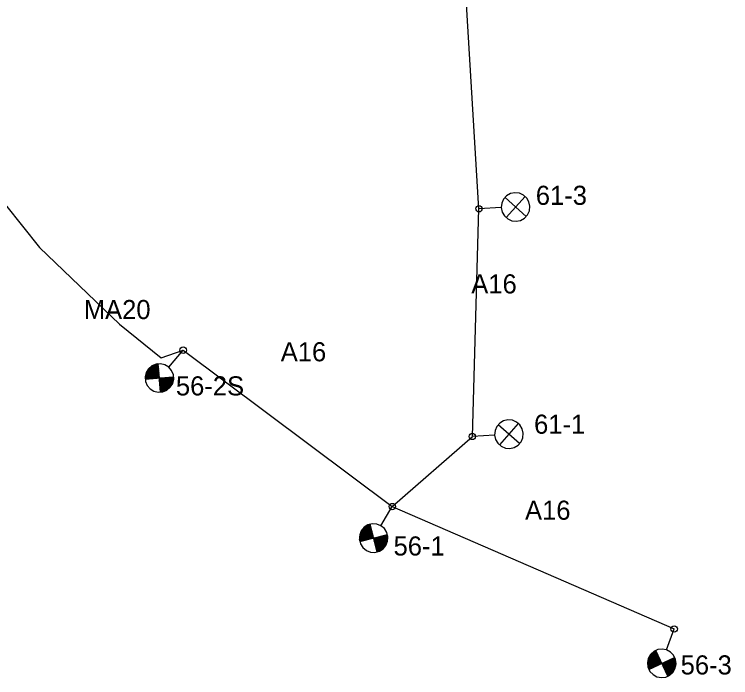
# Model space of a CAD drawing. Extents: x 25497851 to 25498523, y 6686544 to 6687372.
# Drawn here: x 25498410.2 to 25498522.7, y 6687152.3 to 6687256.4 of the extents above; entities that cross this region are included whole.
import ezdxf

# ---------------------------------------------------------------- set-up
doc = ezdxf.new("R2010")
doc.units = 0
for name, color, linetype in [('EL_CABLE_ILMA', 7, 'Continuous'), ('EL_CABLE_MAA', 7, 'Continuous'), ('KEYGWT_ANNOTATION', 7, 'Continuous'), ('Taso 1', 7, 'Continuous'), ('Taso 50', 7, 'Continuous')]:
    doc.layers.add(name, color=color, linetype=linetype)

msp = doc.modelspace()

# ---------------------------------------------------------------- linework, layer by layer
at = {"layer": 'EL_CABLE_ILMA'}
for points in [[(25498469.54, 6687179.13), (25498482.11, 6687190.14), (25498483.15, 6687225.9), (25498480.55, 6687268.5), (25498477.8, 6687311.51), (25498474.29, 6687356.63)], [(25498436.71, 6687203.69), (25498469.54, 6687179.13)], [(25498469.54, 6687179.13), (25498513.79, 6687159.91)]]:
    msp.add_lwpolyline(points, dxfattribs=at)
at = {"layer": 'EL_CABLE_MAA'}
msp.add_lwpolyline([(25498392.6, 6687233.36), (25498390.46, 6687235.76), (25498396.87, 6687241.57), (25498408.81, 6687226.51), (25498414.15, 6687219.81), (25498426.73, 6687207.77), (25498433.27, 6687202.5), (25498436.71, 6687203.69)], dxfattribs=at)
at = {"layer": 'Taso 1'}
for p, q in [((25498490.54, 6687224.68), (25498487.25, 6687227.67)), ((25498490.39, 6687227.82), (25498487.4, 6687224.53)), ((25498486.65, 6687226.07), (25498483.15, 6687225.9)), ((25498434.44, 6687201.03), (25498436.71, 6687203.69)), ((25498433.15, 6687197.1), (25498432.8, 6687201.53)), ((25498430.76, 6687199.14), (25498435.19, 6687199.49)), ((25498489.51, 6687189.03), (25498486.18, 6687191.97)), ((25498489.32, 6687192.17), (25498486.38, 6687188.84)), ((25498485.6, 6687190.36), (25498482.11, 6687190.14)), ((25498467.76, 6687176.12), (25498469.54, 6687179.13)), ((25498467.16, 6687172.03), (25498466.06, 6687176.34)), ((25498464.46, 6687173.63), (25498468.76, 6687174.74)), ((25498512.61, 6687156.62), (25498513.79, 6687159.91)), ((25498512.79, 6687152.49), (25498510.9, 6687156.51)), ((25498509.84, 6687153.56), (25498513.86, 6687155.45))]:
    msp.add_line(p, q, dxfattribs=at)
for points in [[(25498491.14, 6687226.28), (25498491, 6687226.97), (25498490.65, 6687227.58), (25498490.13, 6687228.05), (25498489.49, 6687228.34), (25498488.79, 6687228.42), (25498488.1, 6687228.28), (25498487.49, 6687227.93), (25498487.02, 6687227.41), (25498486.73, 6687226.77), (25498486.65, 6687226.07), (25498486.79, 6687225.38), (25498487.14, 6687224.77), (25498487.66, 6687224.29), (25498488.3, 6687224), (25498489, 6687223.93), (25498489.69, 6687224.07), (25498490.3, 6687224.42), (25498490.78, 6687224.94), (25498491.07, 6687225.58)], [(25498431.52, 6687197.61), (25498432.12, 6687197.24), (25498432.8, 6687197.08), (25498433.5, 6687197.13), (25498434.15, 6687197.4), (25498434.69, 6687197.86), (25498435.06, 6687198.46), (25498435.22, 6687199.14), (25498435.17, 6687199.84), (25498434.9, 6687200.49), (25498434.44, 6687201.03), (25498433.84, 6687201.4), (25498433.15, 6687201.56), (25498432.45, 6687201.51), (25498431.8, 6687201.24), (25498431.27, 6687200.78), (25498430.9, 6687200.18), (25498430.74, 6687199.5), (25498430.79, 6687198.79), (25498431.06, 6687198.14)], [(25498490.09, 6687190.64), (25498489.94, 6687191.33), (25498489.58, 6687191.94), (25498489.05, 6687192.4), (25498488.41, 6687192.68), (25498487.7, 6687192.75), (25498487.02, 6687192.6), (25498486.41, 6687192.24), (25498485.95, 6687191.71), (25498485.67, 6687191.06), (25498485.6, 6687190.36), (25498485.75, 6687189.68), (25498486.11, 6687189.07), (25498486.64, 6687188.6), (25498487.29, 6687188.32), (25498487.99, 6687188.26), (25498488.67, 6687188.41), (25498489.28, 6687188.77), (25498489.75, 6687189.3), (25498490.02, 6687189.94)], [(25498465.47, 6687172.25), (25498466.12, 6687171.99), (25498466.82, 6687171.94), (25498467.51, 6687172.12), (25498468.1, 6687172.5), (25498468.55, 6687173.04), (25498468.81, 6687173.69), (25498468.85, 6687174.4), (25498468.68, 6687175.08), (25498468.3, 6687175.67), (25498467.76, 6687176.12), (25498467.1, 6687176.38), (25498466.4, 6687176.42), (25498465.72, 6687176.25), (25498465.12, 6687175.87), (25498464.67, 6687175.33), (25498464.42, 6687174.68), (25498464.37, 6687173.97), (25498464.55, 6687173.29), (25498464.92, 6687172.7)], [(25498511.08, 6687152.39), (25498511.78, 6687152.26), (25498512.47, 6687152.34), (25498513.11, 6687152.64), (25498513.62, 6687153.13), (25498513.96, 6687153.74), (25498514.09, 6687154.43), (25498514.01, 6687155.13), (25498513.71, 6687155.77), (25498513.22, 6687156.28), (25498512.61, 6687156.62), (25498511.92, 6687156.75), (25498511.22, 6687156.66), (25498510.58, 6687156.37), (25498510.07, 6687155.88), (25498509.73, 6687155.27), (25498509.6, 6687154.58), (25498509.69, 6687153.88), (25498509.99, 6687153.24), (25498510.47, 6687152.73)]]:
    msp.add_lwpolyline(points, close=True, dxfattribs=at)
for centre in [(25498483.15, 6687225.9), (25498436.71, 6687203.69), (25498482.11, 6687190.14), (25498469.54, 6687179.13), (25498513.79, 6687159.91)]:
    msp.add_circle(centre, 0.5, dxfattribs=at)
at = {"layer": 'Taso 50'}
for p, q in [((25498432.91, 6687199.31), (25498431.23, 6687200.74)), ((25498432.84, 6687199.31), (25498431.24, 6687200.67)), ((25498432.98, 6687199.32), (25498431.27, 6687200.78)), ((25498432.97, 6687199.39), (25498431.3, 6687200.82)), ((25498432.97, 6687199.46), (25498431.37, 6687200.82)), ((25498432.96, 6687199.53), (25498431.4, 6687200.86)), ((25498432.96, 6687199.6), (25498431.43, 6687200.9)), ((25498432.95, 6687199.67), (25498431.47, 6687200.94)), ((25498432.94, 6687199.74), (25498431.5, 6687200.98)), ((25498432.94, 6687199.81), (25498431.54, 6687201.01)), ((25498432.93, 6687199.88), (25498431.6, 6687201.02)), ((25498432.93, 6687199.95), (25498431.64, 6687201.06)), ((25498432.92, 6687200.02), (25498431.67, 6687201.09)), ((25498432.92, 6687200.09), (25498431.7, 6687201.13)), ((25498432.91, 6687200.16), (25498431.73, 6687201.17)), ((25498432.91, 6687200.23), (25498431.77, 6687201.21)), ((25498432.9, 6687200.31), (25498431.8, 6687201.24)), ((25498432.89, 6687200.38), (25498431.87, 6687201.25)), ((25498432.89, 6687200.45), (25498431.94, 6687201.26)), ((25498432.88, 6687200.52), (25498431.97, 6687201.3)), ((25498432.88, 6687200.59), (25498432.04, 6687201.3)), ((25498432.87, 6687200.66), (25498432.07, 6687201.34)), ((25498432.87, 6687200.73), (25498432.12, 6687201.36)), ((25498432.86, 6687200.8), (25498432.18, 6687201.38)), ((25498432.86, 6687200.87), (25498432.25, 6687201.39)), ((25498432.85, 6687200.94), (25498432.28, 6687201.43)), ((25498432.84, 6687201.01), (25498432.35, 6687201.43)), ((25498432.84, 6687201.08), (25498432.38, 6687201.47)), ((25498432.83, 6687201.15), (25498432.45, 6687201.48)), ((25498432.83, 6687201.22), (25498432.49, 6687201.51)), ((25498432.82, 6687201.29), (25498432.56, 6687201.52)), ((25498432.82, 6687201.36), (25498432.63, 6687201.52)), ((25498432.81, 6687201.43), (25498432.7, 6687201.53)), ((25498431.22, 6687199.18), (25498430.76, 6687199.57)), ((25498431.36, 6687199.19), (25498430.79, 6687199.68)), ((25498431.29, 6687199.19), (25498430.79, 6687199.61)), ((25498431.5, 6687199.2), (25498430.81, 6687199.79)), ((25498431.43, 6687199.2), (25498430.82, 6687199.72)), ((25498431.64, 6687199.21), (25498430.84, 6687199.89)), ((25498431.57, 6687199.21), (25498430.85, 6687199.82)), ((25498431.78, 6687199.22), (25498430.87, 6687200)), ((25498431.71, 6687199.22), (25498430.87, 6687199.93)), ((25498431.92, 6687199.23), (25498430.89, 6687200.11)), ((25498431.99, 6687199.24), (25498430.9, 6687200.18)), ((25498431.85, 6687199.23), (25498430.9, 6687200.04)), ((25498432.06, 6687199.25), (25498430.92, 6687200.22)), ((25498432.13, 6687199.25), (25498430.95, 6687200.26)), ((25498432.2, 6687199.26), (25498430.99, 6687200.3)), ((25498432.27, 6687199.26), (25498431.02, 6687200.33)), ((25498432.34, 6687199.27), (25498431.05, 6687200.37)), ((25498432.48, 6687199.28), (25498431.08, 6687200.48)), ((25498432.41, 6687199.27), (25498431.08, 6687200.41)), ((25498432.55, 6687199.28), (25498431.11, 6687200.52)), ((25498432.63, 6687199.29), (25498431.14, 6687200.56)), ((25498432.7, 6687199.3), (25498431.18, 6687200.59)), ((25498432.77, 6687199.3), (25498431.21, 6687200.63)), ((25498431.15, 6687199.17), (25498430.73, 6687199.53)), ((25498430.93, 6687199.16), (25498430.74, 6687199.32)), ((25498430.86, 6687199.15), (25498430.75, 6687199.25)), ((25498431.07, 6687199.17), (25498430.77, 6687199.43)), ((25498431, 6687199.16), (25498430.78, 6687199.36)), ((25498432.84, 6687198.85), (25498432.84, 6687198.85)), ((25498434.69, 6687197.86), (25498432.98, 6687199.32)), ((25498434.66, 6687197.82), (25498432.98, 6687199.25)), ((25498434.59, 6687197.81), (25498432.99, 6687199.18)), ((25498434.55, 6687197.78), (25498432.99, 6687199.11)), ((25498434.52, 6687197.74), (25498433, 6687199.04)), ((25498433.01, 6687198.9), (25498434.46, 6687197.66)), ((25498434.42, 6687197.63), (25498433.02, 6687198.83)), ((25498433.02, 6687198.75), (25498434.35, 6687197.62)), ((25498434.32, 6687197.58), (25498433.03, 6687198.68)), ((25498434.29, 6687197.54), (25498433.03, 6687198.61)), ((25498434.49, 6687197.7), (25498433.04, 6687198.93)), ((25498434.26, 6687197.5), (25498433.04, 6687198.54)), ((25498434.22, 6687197.47), (25498433.04, 6687198.47)), ((25498434.72, 6687197.89), (25498433.05, 6687199.32)), ((25498433.12, 6687199.33), (25498434.72, 6687197.97)), ((25498433.19, 6687199.33), (25498434.75, 6687198)), ((25498433.26, 6687199.34), (25498434.78, 6687198.04)), ((25498433.33, 6687199.35), (25498434.81, 6687198.08)), ((25498433.4, 6687199.35), (25498434.85, 6687198.12)), ((25498433.47, 6687199.36), (25498434.87, 6687198.16)), ((25498433.54, 6687199.36), (25498434.87, 6687198.23)), ((25498433.61, 6687199.37), (25498434.91, 6687198.26)), ((25498433.68, 6687199.37), (25498434.94, 6687198.3)), ((25498433.75, 6687199.38), (25498434.97, 6687198.34)), ((25498433.82, 6687199.38), (25498434.96, 6687198.41)), ((25498433.89, 6687199.39), (25498435, 6687198.45)), ((25498433.96, 6687199.4), (25498435.03, 6687198.49)), ((25498434.04, 6687199.4), (25498435.06, 6687198.52)), ((25498434.11, 6687199.41), (25498435.06, 6687198.6)), ((25498434.18, 6687199.41), (25498435.09, 6687198.63)), ((25498434.25, 6687199.42), (25498435.08, 6687198.7)), ((25498434.32, 6687199.42), (25498435.12, 6687198.74)), ((25498434.39, 6687199.43), (25498435.11, 6687198.81)), ((25498434.46, 6687199.43), (25498435.14, 6687198.85)), ((25498434.53, 6687199.44), (25498435.14, 6687198.92)), ((25498434.6, 6687199.45), (25498435.17, 6687198.96)), ((25498434.67, 6687199.45), (25498435.16, 6687199.03)), ((25498434.74, 6687199.46), (25498435.2, 6687199.07)), ((25498434.81, 6687199.46), (25498435.19, 6687199.14)), ((25498434.88, 6687199.47), (25498435.19, 6687199.21)), ((25498434.95, 6687199.47), (25498435.22, 6687199.25)), ((25498435.02, 6687199.48), (25498435.21, 6687199.32)), ((25498435.09, 6687199.48), (25498435.21, 6687199.39)), ((25498433.05, 6687198.4), (25498434.19, 6687197.43)), ((25498433.06, 6687198.33), (25498434.12, 6687197.42)), ((25498433.06, 6687198.26), (25498434.09, 6687197.38)), ((25498433.07, 6687198.19), (25498434.02, 6687197.38)), ((25498433.07, 6687198.12), (25498433.98, 6687197.34)), ((25498433.08, 6687198.05), (25498433.91, 6687197.33)), ((25498433.08, 6687197.98), (25498433.88, 6687197.3)), ((25498433.09, 6687197.91), (25498433.81, 6687197.29)), ((25498433.09, 6687197.84), (25498433.78, 6687197.25)), ((25498433.1, 6687197.77), (25498433.71, 6687197.25)), ((25498433.11, 6687197.7), (25498433.68, 6687197.21)), ((25498433.11, 6687197.63), (25498433.61, 6687197.2)), ((25498433.12, 6687197.56), (25498433.57, 6687197.17)), ((25498433.12, 6687197.49), (25498433.5, 6687197.16)), ((25498433.13, 6687197.41), (25498433.43, 6687197.16)), ((25498433.13, 6687197.34), (25498433.4, 6687197.12)), ((25498433.14, 6687197.27), (25498433.33, 6687197.11)), ((25498433.14, 6687197.2), (25498433.22, 6687197.14)), ((25498466.31, 6687175.35), (25498465.28, 6687175.96)), ((25498466.29, 6687175.42), (25498465.35, 6687175.98)), ((25498466.28, 6687175.48), (25498465.37, 6687176.02)), ((25498466.26, 6687175.55), (25498465.42, 6687176.05)), ((25498466.24, 6687175.62), (25498465.47, 6687176.08)), ((25498466.22, 6687175.69), (25498465.54, 6687176.1)), ((25498466.21, 6687175.76), (25498465.56, 6687176.14)), ((25498466.19, 6687175.83), (25498465.63, 6687176.16)), ((25498466.17, 6687175.9), (25498465.66, 6687176.2)), ((25498466.15, 6687175.96), (25498465.72, 6687176.22)), ((25498466.14, 6687176.03), (25498465.75, 6687176.26)), ((25498466.12, 6687176.1), (25498465.82, 6687176.28)), ((25498466.1, 6687176.17), (25498465.89, 6687176.3)), ((25498466.08, 6687176.24), (25498465.95, 6687176.31)), ((25498465.86, 6687173.99), (25498464.48, 6687174.8)), ((25498465.93, 6687174.01), (25498464.51, 6687174.85)), ((25498465.99, 6687174.03), (25498464.53, 6687174.89)), ((25498466.13, 6687174.06), (25498464.55, 6687175)), ((25498466.2, 6687174.08), (25498464.56, 6687175.05)), ((25498466.06, 6687174.04), (25498464.56, 6687174.93)), ((25498466.27, 6687174.1), (25498464.59, 6687175.09)), ((25498466.34, 6687174.11), (25498464.62, 6687175.13)), ((25498466.41, 6687174.13), (25498464.64, 6687175.17)), ((25498466.54, 6687174.17), (25498464.65, 6687175.29)), ((25498466.61, 6687174.18), (25498464.67, 6687175.33)), ((25498466.47, 6687174.15), (25498464.67, 6687175.22)), ((25498466.59, 6687174.25), (25498464.7, 6687175.37)), ((25498466.58, 6687174.32), (25498464.77, 6687175.39)), ((25498466.56, 6687174.39), (25498464.79, 6687175.43)), ((25498466.54, 6687174.46), (25498464.82, 6687175.48)), ((25498466.52, 6687174.53), (25498464.84, 6687175.52)), ((25498466.51, 6687174.59), (25498464.87, 6687175.56)), ((25498466.49, 6687174.66), (25498464.9, 6687175.6)), ((25498466.47, 6687174.73), (25498464.96, 6687175.62)), ((25498466.45, 6687174.8), (25498464.99, 6687175.67)), ((25498466.44, 6687174.87), (25498465.02, 6687175.71)), ((25498466.42, 6687174.94), (25498465.04, 6687175.75)), ((25498466.4, 6687175.01), (25498465.07, 6687175.79)), ((25498466.38, 6687175.07), (25498465.09, 6687175.84)), ((25498466.36, 6687175.14), (25498465.12, 6687175.87)), ((25498466.35, 6687175.21), (25498465.19, 6687175.9)), ((25498466.33, 6687175.28), (25498465.25, 6687175.92)), ((25498464.83, 6687173.73), (25498464.36, 6687174.01)), ((25498464.9, 6687173.74), (25498464.38, 6687174.05)), ((25498465.04, 6687173.78), (25498464.39, 6687174.16)), ((25498465.17, 6687173.81), (25498464.4, 6687174.27)), ((25498465.45, 6687173.88), (25498464.41, 6687174.5)), ((25498465.31, 6687173.85), (25498464.41, 6687174.38)), ((25498464.97, 6687173.76), (25498464.41, 6687174.09)), ((25498464.62, 6687173.67), (25498464.41, 6687173.8)), ((25498465.65, 6687173.94), (25498464.42, 6687174.68)), ((25498465.58, 6687173.92), (25498464.42, 6687174.61)), ((25498465.24, 6687173.83), (25498464.42, 6687174.32)), ((25498465.1, 6687173.8), (25498464.42, 6687174.2)), ((25498464.76, 6687173.71), (25498464.42, 6687173.91)), ((25498465.72, 6687173.95), (25498464.43, 6687174.72)), ((25498465.38, 6687173.87), (25498464.43, 6687174.43)), ((25498464.56, 6687173.66), (25498464.43, 6687173.73)), ((25498465.52, 6687173.9), (25498464.44, 6687174.54)), ((25498464.69, 6687173.69), (25498464.44, 6687173.84)), ((25498465.79, 6687173.97), (25498464.46, 6687174.76)), ((25498466.55, 6687173.69), (25498466.55, 6687173.69)), ((25498468.55, 6687173.04), (25498466.61, 6687174.18)), ((25498468.52, 6687173), (25498466.63, 6687174.11)), ((25498468.45, 6687172.98), (25498466.65, 6687174.05)), ((25498468.43, 6687172.93), (25498466.66, 6687173.98)), ((25498468.57, 6687173.08), (25498466.68, 6687174.2)), ((25498468.4, 6687172.89), (25498466.68, 6687173.91)), ((25498466.72, 6687173.77), (25498468.35, 6687172.81)), ((25498468.38, 6687172.85), (25498466.74, 6687173.82)), ((25498468.32, 6687172.77), (25498466.74, 6687173.71)), ((25498466.75, 6687174.22), (25498468.56, 6687173.15)), ((25498466.82, 6687174.24), (25498468.58, 6687173.19)), ((25498466.89, 6687174.25), (25498468.61, 6687173.24)), ((25498466.95, 6687174.27), (25498468.63, 6687173.28)), ((25498467.02, 6687174.29), (25498468.66, 6687173.32)), ((25498467.09, 6687174.31), (25498468.68, 6687173.37)), ((25498467.16, 6687174.32), (25498468.67, 6687173.43)), ((25498467.23, 6687174.34), (25498468.69, 6687173.48)), ((25498467.3, 6687174.36), (25498468.72, 6687173.52)), ((25498467.36, 6687174.38), (25498468.74, 6687173.56)), ((25498467.43, 6687174.39), (25498468.72, 6687173.63)), ((25498467.5, 6687174.41), (25498468.75, 6687173.67)), ((25498467.57, 6687174.43), (25498468.77, 6687173.72)), ((25498467.64, 6687174.45), (25498468.8, 6687173.76)), ((25498467.71, 6687174.46), (25498468.78, 6687173.83)), ((25498467.78, 6687174.48), (25498468.81, 6687173.87)), ((25498467.84, 6687174.5), (25498468.79, 6687173.94)), ((25498467.91, 6687174.52), (25498468.82, 6687173.98)), ((25498467.98, 6687174.54), (25498468.8, 6687174.05)), ((25498468.05, 6687174.55), (25498468.82, 6687174.09)), ((25498468.12, 6687174.57), (25498468.81, 6687174.16)), ((25498468.19, 6687174.59), (25498468.83, 6687174.21)), ((25498468.25, 6687174.61), (25498468.81, 6687174.27)), ((25498468.32, 6687174.62), (25498468.84, 6687174.32)), ((25498468.39, 6687174.64), (25498468.82, 6687174.39)), ((25498468.46, 6687174.66), (25498468.8, 6687174.45)), ((25498468.53, 6687174.68), (25498468.83, 6687174.5)), ((25498468.6, 6687174.69), (25498468.81, 6687174.57)), ((25498468.67, 6687174.71), (25498468.79, 6687174.63)), ((25498466.75, 6687173.64), (25498468.26, 6687172.74)), ((25498468.23, 6687172.7), (25498466.77, 6687173.57)), ((25498468.21, 6687172.66), (25498466.79, 6687173.5)), ((25498468.18, 6687172.62), (25498466.8, 6687173.43)), ((25498468.16, 6687172.57), (25498466.82, 6687173.36)), ((25498466.84, 6687173.29), (25498468.13, 6687172.53)), ((25498466.86, 6687173.22), (25498468.06, 6687172.51)), ((25498466.87, 6687173.16), (25498468.04, 6687172.47)), ((25498466.89, 6687173.09), (25498467.97, 6687172.45)), ((25498466.91, 6687173.02), (25498467.94, 6687172.41)), ((25498466.93, 6687172.95), (25498467.87, 6687172.39)), ((25498466.95, 6687172.88), (25498467.85, 6687172.35)), ((25498466.96, 6687172.81), (25498467.78, 6687172.33)), ((25498466.98, 6687172.75), (25498467.76, 6687172.29)), ((25498467, 6687172.68), (25498467.69, 6687172.27)), ((25498467.02, 6687172.61), (25498467.66, 6687172.23)), ((25498467.03, 6687172.54), (25498467.59, 6687172.21)), ((25498467.05, 6687172.47), (25498467.57, 6687172.17)), ((25498467.07, 6687172.4), (25498467.5, 6687172.15)), ((25498467.09, 6687172.33), (25498467.43, 6687172.13)), ((25498467.1, 6687172.27), (25498467.4, 6687172.09)), ((25498467.12, 6687172.2), (25498467.34, 6687172.07)), ((25498467.14, 6687172.13), (25498467.22, 6687172.08)), ((25498511.54, 6687155.14), (25498509.99, 6687155.7)), ((25498511.51, 6687155.21), (25498510.01, 6687155.75)), ((25498511.48, 6687155.27), (25498510.03, 6687155.8)), ((25498511.45, 6687155.34), (25498510.04, 6687155.84)), ((25498511.42, 6687155.4), (25498510.07, 6687155.88)), ((25498511.39, 6687155.46), (25498510.12, 6687155.92)), ((25498511.36, 6687155.53), (25498510.19, 6687155.95)), ((25498511.33, 6687155.59), (25498510.2, 6687156)), ((25498511.3, 6687155.66), (25498510.27, 6687156.03)), ((25498511.27, 6687155.72), (25498510.29, 6687156.08)), ((25498511.24, 6687155.78), (25498510.32, 6687156.12)), ((25498511.21, 6687155.85), (25498510.37, 6687156.15)), ((25498511.18, 6687155.91), (25498510.43, 6687156.18)), ((25498511.15, 6687155.98), (25498510.45, 6687156.23)), ((25498511.12, 6687156.04), (25498510.51, 6687156.26)), ((25498511.09, 6687156.1), (25498510.53, 6687156.31)), ((25498511.06, 6687156.17), (25498510.59, 6687156.34)), ((25498511.03, 6687156.23), (25498510.61, 6687156.38)), ((25498511, 6687156.3), (25498510.67, 6687156.41)), ((25498510.97, 6687156.36), (25498510.74, 6687156.44)), ((25498510.94, 6687156.42), (25498510.8, 6687156.47)), ((25498511.01, 6687154.11), (25498509.6, 6687154.62)), ((25498510.95, 6687154.08), (25498509.6, 6687154.58)), ((25498511.08, 6687154.14), (25498509.62, 6687154.67)), ((25498511.14, 6687154.17), (25498509.64, 6687154.71)), ((25498511.21, 6687154.2), (25498509.65, 6687154.76)), ((25498511.4, 6687154.29), (25498509.66, 6687154.92)), ((25498511.46, 6687154.32), (25498509.67, 6687154.97)), ((25498511.27, 6687154.23), (25498509.67, 6687154.81)), ((25498511.53, 6687154.35), (25498509.69, 6687155.01)), ((25498511.33, 6687154.26), (25498509.69, 6687154.86)), ((25498511.78, 6687154.47), (25498509.71, 6687155.22)), ((25498511.59, 6687154.38), (25498509.71, 6687155.06)), ((25498511.65, 6687154.41), (25498509.72, 6687155.11)), ((25498511.85, 6687154.5), (25498509.73, 6687155.27)), ((25498511.72, 6687154.44), (25498509.74, 6687155.15)), ((25498511.82, 6687154.57), (25498509.75, 6687155.31)), ((25498511.79, 6687154.63), (25498509.81, 6687155.34)), ((25498511.76, 6687154.7), (25498509.83, 6687155.39)), ((25498511.73, 6687154.76), (25498509.84, 6687155.44)), ((25498511.7, 6687154.82), (25498509.86, 6687155.48)), ((25498511.66, 6687154.89), (25498509.88, 6687155.53)), ((25498511.63, 6687154.95), (25498509.9, 6687155.58)), ((25498511.6, 6687155.02), (25498509.96, 6687155.61)), ((25498511.57, 6687155.08), (25498509.98, 6687155.66)), ((25498511.97, 6687154.56), (25498513.95, 6687153.85)), ((25498512.04, 6687154.59), (25498513.97, 6687153.9)), ((25498512.1, 6687154.62), (25498513.98, 6687153.95)), ((25498512.17, 6687154.65), (25498514, 6687153.99)), ((25498512.23, 6687154.68), (25498514.02, 6687154.04)), ((25498512.29, 6687154.71), (25498514.03, 6687154.09)), ((25498512.36, 6687154.74), (25498514, 6687154.15)), ((25498512.42, 6687154.77), (25498514.02, 6687154.2)), ((25498512.49, 6687154.8), (25498514.04, 6687154.25)), ((25498512.55, 6687154.84), (25498514.05, 6687154.29)), ((25498512.61, 6687154.87), (25498514.02, 6687154.36)), ((25498512.68, 6687154.9), (25498514.04, 6687154.4)), ((25498512.74, 6687154.93), (25498514.06, 6687154.45)), ((25498512.81, 6687154.96), (25498514.08, 6687154.5)), ((25498512.87, 6687154.99), (25498514.05, 6687154.56)), ((25498512.93, 6687155.02), (25498514.06, 6687154.61)), ((25498513, 6687155.05), (25498514.03, 6687154.67)), ((25498513.06, 6687155.08), (25498514.05, 6687154.72)), ((25498513.13, 6687155.11), (25498514.02, 6687154.78)), ((25498513.19, 6687155.14), (25498514.04, 6687154.83)), ((25498513.25, 6687155.17), (25498514.01, 6687154.9)), ((25498513.32, 6687155.2), (25498514.02, 6687154.94)), ((25498513.38, 6687155.23), (25498513.99, 6687155.01)), ((25498513.45, 6687155.26), (25498514.01, 6687155.05)), ((25498513.51, 6687155.29), (25498513.98, 6687155.12)), ((25498513.57, 6687155.32), (25498513.95, 6687155.18)), ((25498513.64, 6687155.35), (25498513.97, 6687155.23)), ((25498513.7, 6687155.38), (25498513.94, 6687155.29)), ((25498513.76, 6687155.41), (25498513.91, 6687155.36)), ((25498510.89, 6687154.05), (25498509.62, 6687154.51)), ((25498510.76, 6687153.99), (25498509.63, 6687154.4)), ((25498510.63, 6687153.93), (25498509.64, 6687154.29)), ((25498510.82, 6687154.02), (25498509.65, 6687154.45)), ((25498510.69, 6687153.96), (25498509.66, 6687154.33)), ((25498510.5, 6687153.87), (25498509.66, 6687154.18)), ((25498510.18, 6687153.72), (25498509.66, 6687153.91)), ((25498510.57, 6687153.9), (25498509.67, 6687154.22)), ((25498510.37, 6687153.81), (25498509.67, 6687154.07)), ((25498510.25, 6687153.75), (25498509.68, 6687153.95)), ((25498510.44, 6687153.84), (25498509.69, 6687154.11)), ((25498510.31, 6687153.78), (25498509.7, 6687154)), ((25498510.12, 6687153.69), (25498509.74, 6687153.83)), ((25498509.99, 6687153.63), (25498509.75, 6687153.72)), ((25498510.05, 6687153.66), (25498509.77, 6687153.76)), ((25498509.93, 6687153.6), (25498509.78, 6687153.65)), ((25498513.96, 6687153.74), (25498511.85, 6687154.5)), ((25498513.95, 6687153.69), (25498511.88, 6687154.44)), ((25498511.88, 6687154.01), (25498511.88, 6687154.01)), ((25498513.98, 6687153.79), (25498511.91, 6687154.53)), ((25498513.88, 6687153.66), (25498511.91, 6687154.38)), ((25498513.86, 6687153.62), (25498511.94, 6687154.31)), ((25498513.85, 6687153.57), (25498511.97, 6687154.25)), ((25498512.03, 6687154.12), (25498513.81, 6687153.48)), ((25498513.83, 6687153.52), (25498512.04, 6687154.17)), ((25498513.79, 6687153.43), (25498512.06, 6687154.06)), ((25498512.09, 6687153.99), (25498513.73, 6687153.4)), ((25498513.72, 6687153.35), (25498512.12, 6687153.93)), ((25498513.7, 6687153.31), (25498512.15, 6687153.86)), ((25498513.68, 6687153.26), (25498512.18, 6687153.8)), ((25498513.67, 6687153.21), (25498512.21, 6687153.74)), ((25498512.24, 6687153.67), (25498513.65, 6687153.16)), ((25498512.27, 6687153.61), (25498513.58, 6687153.13)), ((25498512.3, 6687153.54), (25498513.57, 6687153.09)), ((25498512.33, 6687153.48), (25498513.5, 6687153.06)), ((25498512.36, 6687153.42), (25498513.49, 6687153.01)), ((25498512.39, 6687153.35), (25498513.42, 6687152.98)), ((25498512.42, 6687153.29), (25498513.41, 6687152.93)), ((25498512.45, 6687153.22), (25498513.34, 6687152.9)), ((25498512.48, 6687153.16), (25498513.32, 6687152.86)), ((25498512.51, 6687153.1), (25498513.26, 6687152.83)), ((25498512.54, 6687153.03), (25498513.24, 6687152.78)), ((25498512.57, 6687152.97), (25498513.18, 6687152.75)), ((25498512.6, 6687152.9), (25498513.16, 6687152.7)), ((25498512.63, 6687152.84), (25498513.1, 6687152.67)), ((25498512.66, 6687152.78), (25498513.03, 6687152.64)), ((25498512.69, 6687152.71), (25498513.02, 6687152.59)), ((25498512.72, 6687152.65), (25498512.95, 6687152.56)), ((25498512.75, 6687152.58), (25498512.84, 6687152.55))]:
    msp.add_line(p, q, dxfattribs=at)

# ---------------------------------------------------------------- texts
at = {"layer": 'KEYGWT_ANNOTATION'}
for s, p in [('61-3', (25498492.07, 6687226.51)), ('A16', (25498481.94, 6687212.6)), ('MA20', (25498421.11, 6687208.57)), ('A16', (25498452.03, 6687201.94)), ('56-2S', (25498435.57, 6687196.58)), ('61-1', (25498491.8, 6687190.57)), ('A16', (25498490.38, 6687177.06)), ('56-1', (25498469.74, 6687171.44)), ('56-3', (25498514.81, 6687152.76))]:
    msp.add_text(s, height=3, dxfattribs=at).set_placement(p)

doc.saveas('drawing.dxf')
